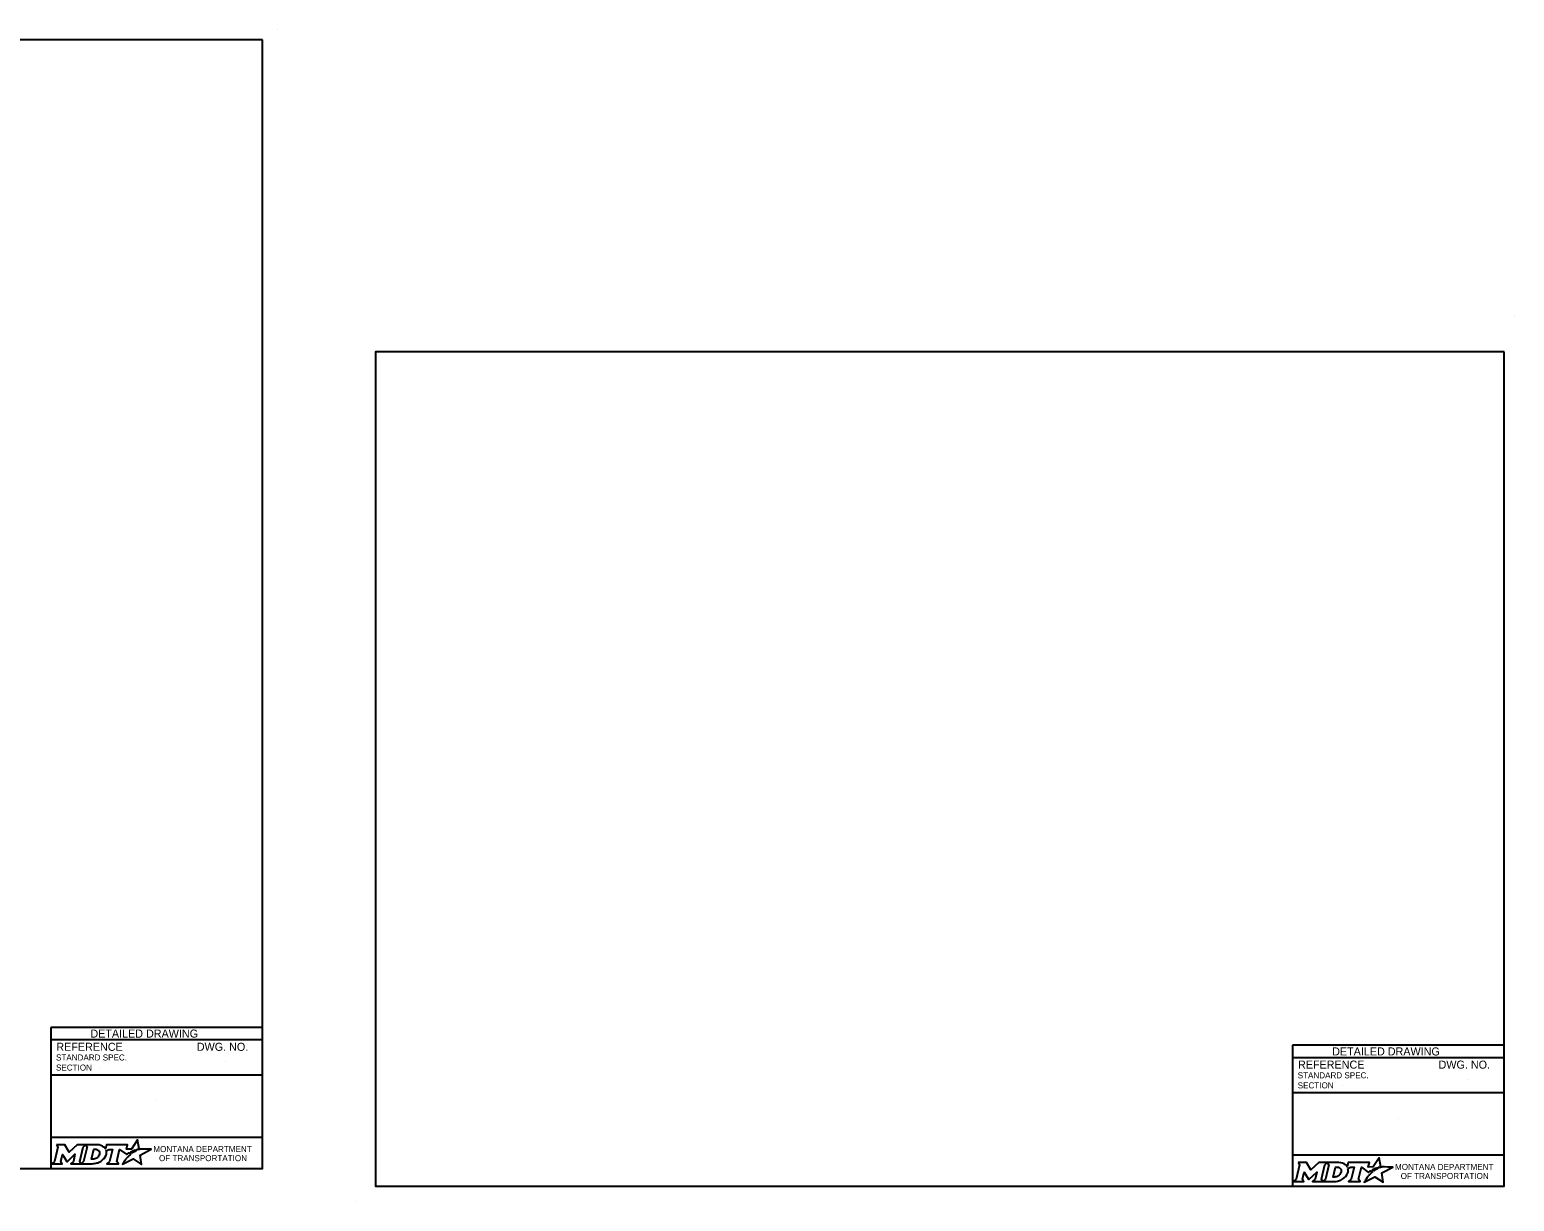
# Model space of a CAD drawing. Extents: x 49991.4 to 50021, y 49987.6 to 50011.4.
# Drawn here: x 50006.3 to 50021.04, y 49999.74 to 50011.36 of the extents above; entities that cross this region are included whole.
import ezdxf

# ---------------------------------------------------------------- set-up
doc = ezdxf.new("R2010")
doc.units = 0
for name, color, linetype in [('Default', 7, 'Continuous'), ('Level 1', 7, 'Continuous'), ('Level 2', 7, 'Continuous'), ('Level 4', 7, 'Continuous')]:
    doc.layers.add(name, color=color, linetype=linetype)

msp = doc.modelspace()

# ---------------------------------------------------------------- linework, layer by layer
at = {"layer": 'Default'}
for points in [[(50018.893, 50000.121), (50018.907, 50000.097), (50018.874, 49999.954), (50018.848, 49999.931), (50018.95, 49999.931), (50018.936, 49999.954), (50018.952, 50000.024), (50018.996, 49999.955), (50019.002, 49999.955), (50019.077, 50000.025), (50019.06, 49999.954), (50019.035, 49999.932), (50019.137, 49999.932), (50019.123, 49999.955), (50019.156, 50000.097)], [(50019.156, 50000.097), (50019.182, 50000.121), (50019.099, 50000.121), (50019.02, 50000.048), (50018.975, 50000.12), (50018.893, 50000.121)], [(50019.295, 50000.121), (50019.182, 50000.121), (50019.196, 50000.098), (50019.163, 49999.954), (50019.137, 49999.932), (50019.248, 49999.932)], [(50019.319, 50000.034), (50019.318, 50000.026), (50019.315, 50000.017), (50019.311, 50000.008), (50019.305, 50000.001), (50019.299, 49999.994), (50019.291, 49999.988), (50019.282, 49999.983), (50019.273, 49999.979), (50019.264, 49999.977), (50019.255, 49999.976), (50019.239, 49999.976), (50019.263, 50000.076), (50019.279, 50000.076), (50019.286, 50000.075), (50019.294, 50000.073), (50019.301, 50000.07), (50019.307, 50000.066), (50019.311, 50000.061), (50019.315, 50000.055), (50019.318, 50000.049), (50019.319, 50000.042), (50019.32, 50000.038), (50019.319, 50000.034)], [(50019.7, 50000.068), (50019.69, 50000.074), (50019.702, 50000.076), (50019.713, 50000.078), (50019.696, 50000.168), (50019.636, 50000.077), (50019.589, 50000.076), (50019.599, 50000.12), (50019.39, 50000.121), (50019.38, 50000.078), (50019.374, 50000.086)], [(50019.387, 50000.062), (50019.411, 50000.075), (50019.448, 50000.075), (50019.42, 49999.954), (50019.392, 49999.931), (50019.508, 49999.931), (50019.491, 49999.954), (50019.52, 50000.075), (50019.591, 50000.023), (50019.612, 50000.038), (50019.632, 50000.027)], [(50019.576, 49999.971), (50019.561, 49999.947), (50019.556, 49999.939), (50019.55, 49999.931), (50019.548, 49999.926), (50019.653, 49999.979), (50019.737, 49999.924), (50019.724, 50000.017), (50019.831, 50000.075), (50019.782, 50000.076), (50019.751, 50000.077), (50019.731, 50000.077), (50019.724, 50000.075), (50019.719, 50000.074), (50019.711, 50000.072), (50019.7, 50000.068)], [(50019.293, 49999.939), (50019.302, 49999.942), (50019.315, 49999.947), (50019.335, 49999.958)], [(50019.59, 49999.987), (50019.59, 49999.987)], [(50019.65, 50000.04), (50019.648, 50000.039), (50019.629, 50000.048), (50019.639, 50000.054), (50019.644, 50000.056), (50019.652, 50000.06), (50019.658, 50000.063), (50019.666, 50000.066), (50019.673, 50000.068), (50019.685, 50000.061), (50019.681, 50000.059), (50019.676, 50000.056), (50019.672, 50000.054), (50019.667, 50000.051), (50019.665, 50000.05), (50019.662, 50000.049), (50019.66, 50000.047), (50019.658, 50000.046), (50019.655, 50000.044), (50019.652, 50000.042), (50019.65, 50000.04)]]:
    msp.add_lwpolyline(points, dxfattribs=at)
for centre, radius, start, end in [((50019.274, 50000.059), 0.118, 300.9103, 339.1383), ((50019.319, 50000.042), 0.0709, 339.5329, 15.8582)]:
    msp.add_arc(centre, radius, start, end, dxfattribs=at)
for centre, major_axis, ratio, start_param, end_param in [((50019.293, 50000.073), (0.0834, -0.0037), 0.568097, 0.61298, 1.570796), ((50019.349, 50000.081), (0.0361, -0.0295), 0.469099, 1.225588, 1.570796), ((50019.248, 50000.08), (0, 0.148), 0.987302, 3.139398, 3.456847), ((50019.583, 49999.979), (-0.00694, -0.00806), 0.008222, 0, 3.137361), ((50019.6, 49999.997), (-0.0098, -0.0102), 0.016458, 3.141593, 6.279097), ((50019.621, 50000.017), (-0.0112, -0.0097), 0.021651, 3.157348, 6.283185)]:
    msp.add_ellipse(centre, major_axis=major_axis, ratio=ratio, start_param=start_param, end_param=end_param, dxfattribs=at)
at = {"layer": 'Level 1'}
for p, q in [((50008.765, 50011.363), (50008.765, 50011.363)), ((50021.038, 50008.524), (50021.038, 50008.524)), ((50009.537, 49999.736), (50009.537, 49999.736))]:
    msp.add_line(p, q, dxfattribs=at)
for points in [[(50008.615, 50011.263), (50000.336, 50011.263), (50000.336, 50000.062), (50008.615, 50000.062)], [(50020.938, 50008.165), (50009.737, 50008.165), (50009.737, 49999.886), (50020.938, 49999.886)]]:
    msp.add_lwpolyline(points, close=True, dxfattribs=at)
at = {"layer": 'Level 2'}
for p, q in [((50008.615, 50001.462), (50006.515, 50001.462)), ((50006.515, 50001.462), (50006.515, 50000.062)), ((50008.615, 50001.337), (50006.515, 50001.337)), ((50008.251, 50001.122), (50008.251, 50001.122)), ((50008.615, 50000.987), (50006.515, 50000.987)), ((50007.009, 50001.063), (50007.009, 50001.063)), ((50007.565, 50000.738), (50007.565, 50000.738)), ((50008.615, 50000.369), (50006.515, 50000.369))]:
    msp.add_line(p, q, dxfattribs=at)
for points in [[(50006.57, 50000.297), (50006.584, 50000.274), (50006.551, 50000.131), (50006.525, 50000.108), (50006.627, 50000.108), (50006.613, 50000.131), (50006.629, 50000.201), (50006.673, 50000.132), (50006.678, 50000.132), (50006.753, 50000.202), (50006.737, 50000.13), (50006.712, 50000.108), (50006.814, 50000.108), (50006.8, 50000.132), (50006.833, 50000.274)], [(50006.833, 50000.274), (50006.859, 50000.297), (50006.776, 50000.297), (50006.697, 50000.224), (50006.652, 50000.297), (50006.57, 50000.297)], [(50006.972, 50000.297), (50006.859, 50000.297), (50006.873, 50000.275), (50006.839, 50000.131), (50006.814, 50000.108), (50006.925, 50000.108)], [(50006.996, 50000.211), (50006.995, 50000.203), (50006.992, 50000.193), (50006.988, 50000.185), (50006.982, 50000.178), (50006.976, 50000.171), (50006.968, 50000.164), (50006.959, 50000.16), (50006.95, 50000.156), (50006.941, 50000.154), (50006.932, 50000.153), (50006.916, 50000.153), (50006.94, 50000.253), (50006.956, 50000.253), (50006.963, 50000.252), (50006.971, 50000.25), (50006.977, 50000.247), (50006.983, 50000.243), (50006.988, 50000.238), (50006.992, 50000.232), (50006.995, 50000.226), (50006.996, 50000.218), (50006.996, 50000.215), (50006.996, 50000.211)], [(50007.377, 50000.245), (50007.367, 50000.25), (50007.378, 50000.253), (50007.39, 50000.255), (50007.373, 50000.345), (50007.313, 50000.254), (50007.266, 50000.253), (50007.276, 50000.297), (50007.067, 50000.297), (50007.057, 50000.255), (50007.051, 50000.263)], [(50007.064, 50000.238), (50007.088, 50000.251), (50007.125, 50000.251), (50007.097, 50000.131), (50007.069, 50000.108), (50007.185, 50000.108), (50007.168, 50000.131), (50007.196, 50000.251), (50007.268, 50000.2), (50007.289, 50000.215), (50007.309, 50000.204)], [(50007.253, 50000.148), (50007.237, 50000.124), (50007.233, 50000.116), (50007.227, 50000.107), (50007.225, 50000.103), (50007.33, 50000.156), (50007.414, 50000.101), (50007.401, 50000.194), (50007.508, 50000.252), (50007.458, 50000.253), (50007.428, 50000.253), (50007.407, 50000.254), (50007.401, 50000.252), (50007.396, 50000.251), (50007.387, 50000.249), (50007.377, 50000.245)], [(50007.327, 50000.217), (50007.324, 50000.215), (50007.306, 50000.225), (50007.316, 50000.231), (50007.32, 50000.233), (50007.329, 50000.237), (50007.335, 50000.239), (50007.343, 50000.243), (50007.35, 50000.245), (50007.362, 50000.238), (50007.358, 50000.236), (50007.353, 50000.233), (50007.349, 50000.231), (50007.344, 50000.228), (50007.342, 50000.227), (50007.339, 50000.225), (50007.337, 50000.224), (50007.334, 50000.222), (50007.332, 50000.221), (50007.329, 50000.219), (50007.327, 50000.217)], [(50006.97, 50000.116), (50006.979, 50000.118), (50006.992, 50000.124), (50007.012, 50000.135)], [(50007.267, 50000.164), (50007.267, 50000.164)]]:
    msp.add_lwpolyline(points, dxfattribs=at)
for centre, radius, start, end in [((50006.995, 50000.219), 0.0709, 339.5329, 15.8582), ((50006.951, 50000.236), 0.118, 300.9103, 339.1383)]:
    msp.add_arc(centre, radius, start, end, dxfattribs=at)
for centre, major_axis, ratio, start_param, end_param in [((50006.97, 50000.25), (0.0834, -0.0037), 0.568097, 0.61298, 1.570796), ((50007.026, 50000.257), (0.0361, -0.0295), 0.469099, 1.225588, 1.570796), ((50006.925, 50000.257), (0, 0.148), 0.987302, 3.139398, 3.456847), ((50007.26, 50000.156), (-0.00694, -0.00806), 0.008222, 0, 3.137361), ((50007.276, 50000.174), (-0.0098, -0.0102), 0.016458, 3.141593, 6.279097), ((50007.297, 50000.194), (-0.0112, -0.0097), 0.021651, 3.157348, 6.283185)]:
    msp.add_ellipse(centre, major_axis=major_axis, ratio=ratio, start_param=start_param, end_param=end_param, dxfattribs=at)
at = {"layer": 'Level 4'}
for p, q in [((50020.938, 50001.286), (50018.838, 50001.286)), ((50018.838, 50001.286), (50018.838, 49999.886)), ((50020.938, 50001.161), (50018.838, 50001.161)), ((50020.938, 50000.811), (50018.838, 50000.811)), ((50019.332, 50000.886), (50019.332, 50000.886)), ((50020.574, 50000.946), (50020.574, 50000.946)), ((50019.888, 50000.562), (50019.888, 50000.562)), ((50020.938, 50000.193), (50018.838, 50000.193))]:
    msp.add_line(p, q, dxfattribs=at)

# ---------------------------------------------------------------- texts
at = {"layer": 'Default'}
for s, p in [('MONTANA DEPARTMENT', (50019.854, 50000.047)), ('OF TRANSPORTATION', (50019.91, 49999.957))]:
    msp.add_text(s, height=0.06, dxfattribs=at).set_placement(p)
at = {"layer": 'Level 2'}
for s, height, p in [('DETAILED DRAWING', 0.0799, (50006.906, 50001.36)), ('REFERENCE', 0.08, (50006.568, 50001.229)), ('DWG. NO.', 0.08, (50007.962, 50001.229)), ('STANDARD SPEC.', 0.06, (50006.565, 50001.133)), ('SECTION', 0.06, (50006.565, 50001.033)), ('MONTANA DEPARTMENT', 0.06, (50007.531, 50000.224)), ('OF TRANSPORTATION', 0.06, (50007.587, 50000.134))]:
    msp.add_text(s, height=height, dxfattribs=at).set_placement(p)
at = {"layer": 'Level 4'}
for s, height, p in [('DETAILED DRAWING', 0.0799, (50019.23, 50001.183)), ('REFERENCE', 0.08, (50018.891, 50001.052)), ('DWG. NO.', 0.08, (50020.286, 50001.052)), ('STANDARD SPEC.', 0.06, (50018.888, 50000.956)), ('SECTION', 0.06, (50018.888, 50000.856))]:
    msp.add_text(s, height=height, dxfattribs=at).set_placement(p)

doc.saveas('drawing.dxf')
